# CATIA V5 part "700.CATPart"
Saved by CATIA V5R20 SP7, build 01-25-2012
Part number: skl_general
Publications: "Pa", "Pc", "H", "A", "F", "E", "B", "B2", "C", "M", "N", "Plan.1", "J", "I"
Bounding box of the stored display mesh (mm): x -524.226 to 524.226, y -390 to 772.62, z 0 to 0
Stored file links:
  U:\IAO\thinkmotion catia2\700.CATPart
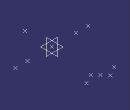
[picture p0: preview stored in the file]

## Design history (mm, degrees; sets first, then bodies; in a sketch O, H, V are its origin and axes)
Parameters
  Pa = 700 mm
  Pc = 390 mm
Set1
  Point1 "H": (0, 0, 0)
  Point2 "A": (0, 700 {= Pa}, 0)
  Point3 "F": (200, 700 {= Pa}, 0)
  Point4 "E": (-200, 700 {= Pa}, 0)
  Point5 "B": (68.75, 627.38 {= Pa -72.62mm}, 0)
  Point6 "B2": (-68.75, 772.62 {= Pa +72.62mm}, 0)
  Point7 "C": (0, -390 {= -Pc}, 0)
  Point8 "M": (350, 0, 0)
  Point9 "N": (-350, 0, 0)
  Plane1: type Offset, RefPlane xy-plane, Offset 0
  Point10 "J": (524.226, 0, 0)
  Point11 "I": (-524.226, 0, 0)
Body1 (main body)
